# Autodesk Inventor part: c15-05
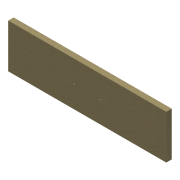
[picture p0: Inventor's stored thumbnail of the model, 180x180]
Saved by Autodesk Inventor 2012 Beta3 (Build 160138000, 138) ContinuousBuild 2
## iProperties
Created: 2011-02
Part Number: c15-05
Material: Default
Document SubType Name: Modeling
Designer: Beta-8540w
Density: 1 g/cm^3
Author: Beta-8540w
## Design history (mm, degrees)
sketch "Sketch1"
  geometry: L1 (-228.6, -63.5)-(228.6, -63.5); L2 (228.6, -63.5)-(228.6, 63.5); L3 (228.6, 63.5)-(-228.6, 63.5); L4 (-228.6, 63.5)-(-228.6, -63.5); 3 further points
  constraints: 8 end point, 2 midpoint, 2 parallel, 1 horizontal, 1 horizontal alignment, 1 perpendicular, 1 vertical alignment
  dimensions: "width" = 457.2 distance of L3.end L2.end; "height" = 127 distance of L2.end L1.end
extrude "Drawer Face" new body sketch "Sketch1" distance "d2" = 15.875; taper "d3" = 0 deg
sketch "Sketch2"
  geometry: 1 further point
hole "Single Hole Pull" sketch "Sketch2" at (0, 0) diameter "d4" = 4.4958; stored, may be unused: countersink angle "d8" = 82 deg, drill point angle "d10" = 118 deg; dims "d5" = 19.05, "d9" = 25.4, "d72" = 8.4328, "d73" = 6.35
sketch "Sketch3"
  geometry: L1 (-38.1, 0)-(38.1, 0); 2 further points
  constraints: 2 end point, 1 coincident, 1 horizontal, 1 midpoint
  dimensions: "d6" = 76.2 distance of L1.start L1.end
hole "Double Hole Pull" sketch "Sketch3" at (-38.1, 0), (38.1, 0) diameter "d7" = 4.4958; stored, may be unused: countersink angle "d16" = 82 deg, drill point angle "d18" = 118 deg; dims "d13" = 19.05, "d14" = 8.4328, "d15" = 6.35, "d17" = 25.4
body "Solid1"
